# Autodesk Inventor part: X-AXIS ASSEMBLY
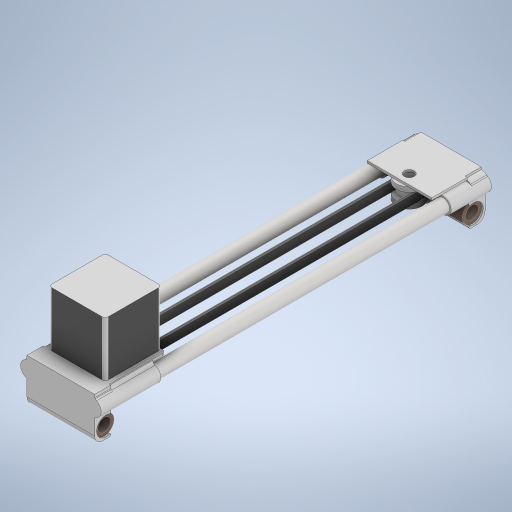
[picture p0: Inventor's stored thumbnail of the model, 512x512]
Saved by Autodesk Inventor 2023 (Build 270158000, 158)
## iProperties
Created: 2025-07
Part Number: X-AXIS ASSEMBLY
Material: Generic
Document SubType Name: Modeling
Designer: erjon
Density: 1 g/cm^3
Appearance: Default
Author: erjon
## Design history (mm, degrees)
feature "Base1"
feature "Base2"
feature "Base3"
feature "Base4"
feature "Base5"
feature "Base6"
feature "Base7"
feature "Base8"
feature "Base9"
feature "Base10"
feature "Base11"
feature "Base12"
feature "Base13"
feature "Base14"
body "Solid1"
body "Solid2"
body "Solid3"
body "Solid4"
body "Solid5"
body "Solid6"
body "Solid7"
body "Solid8"
body "Solid9"
body "Solid10"
body "Solid11"
body "Solid12"
body "Solid13"
body "Solid14"
